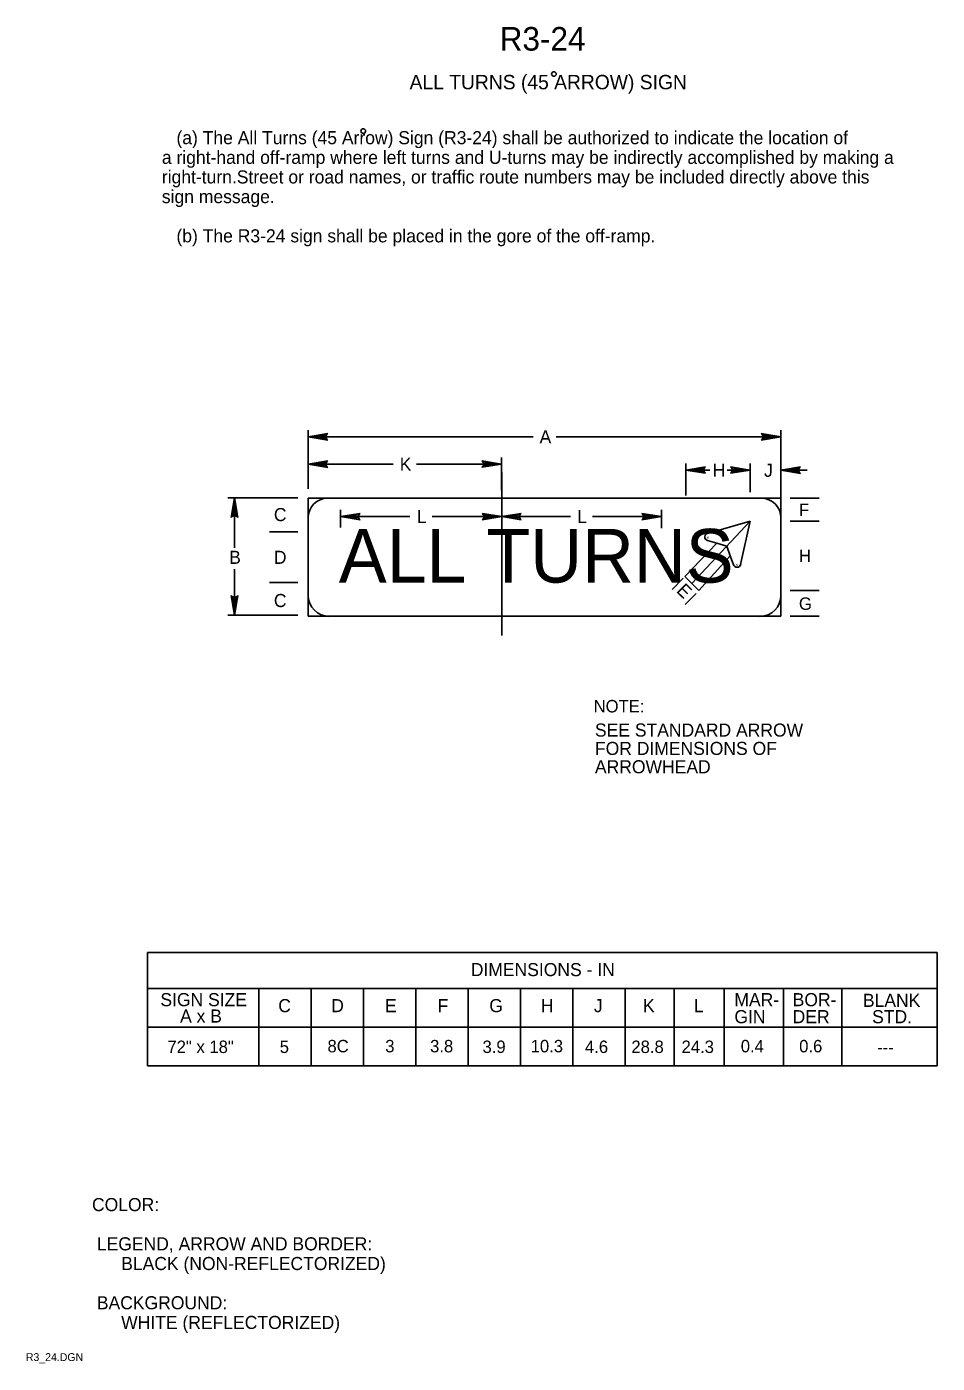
# Model space of a CAD drawing. Extents: x 0.5 to 7.3, y 0.2 to 10.2.
import ezdxf

# ---------------------------------------------------------------- set-up
doc = ezdxf.new("R2010")
doc.units = 0
for name, color, linetype in [('1', 7, 'Continuous'), ('11', 7, 'Continuous'), ('12', 7, 'Continuous'), ('2', 7, 'Continuous'), ('3', 7, 'Continuous')]:
    doc.layers.add(name, color=color, linetype=linetype)

# ---------------------------------------------------------------- blocks, each defined once
blk = doc.blocks.new('RARROW')
at = {"layer": '3'}
for p, q in [((-84.9, 11.2), (-89.2, 15.1)), ((-89.2, 15.1), (0, 0)), ((0, 0), (-89.2, -14.9)), ((-84.9, 11.2), (-81.7, 4.8)), ((0, 0), (-84.9, 11.2)), ((-84.6, -10.6), (0, 0)), ((-81.7, 4.8), (0, 0)), ((0, 0), (-81.7, -4.3)), ((-89.2, -14.9), (-84.6, -10.6)), ((-81.7, -4.3), (-84.6, -10.6))]:
    blk.add_line(p, q, dxfattribs=at)

msp = doc.modelspace()

# ---------------------------------------------------------------- linework, layer by layer
at = {"layer": '1'}
for centre in [(4.461, 9.849), (3.028, 9.42)]:
    msp.add_circle(centre, 0.0174, dxfattribs=at)
at = {"layer": '11'}
for p, q in [((2.614, 6.502), (2.614, 6.66)), ((2.614, 6.66), (2.772, 6.66)), ((6.009, 6.66), (6.167, 6.66)), ((6.167, 6.66), (6.167, 6.502)), ((2.614, 5.772), (2.614, 5.929)), ((6.167, 5.929), (6.167, 5.772)), ((2.772, 5.772), (2.614, 5.772)), ((6.167, 5.772), (6.009, 5.772))]:
    msp.add_line(p, q, dxfattribs=at)
at = {"layer": '12'}
for p, q in [((5.935, 6.487), (5.616, 6.395)), ((5.864, 6.161), (5.935, 6.487)), ((5.614, 6.341), (5.684, 6.321)), ((5.684, 6.321), (5.444, 6.07)), ((5.549, 5.966), (5.786, 6.225)), ((5.786, 6.225), (5.811, 6.159)), ((5.444, 6.07), (5.549, 5.966))]:
    msp.add_line(p, q, dxfattribs=at)
for centre, radius, start, end in [((5.623, 6.368), 0.0282, 104.7971, 250.7977), ((5.837, 6.168), 0.0281, 198.1274, 346.0897)]:
    msp.add_arc(centre, radius, start, end, dxfattribs=at)
at = {"layer": '3'}
for p, q in [((2.614, 6.88), (2.614, 7.17)), ((6.167, 6.722), (6.167, 7.17)), ((4.304, 7.121), (2.614, 7.121)), ((4.477, 7.121), (6.167, 7.121)), ((2.614, 6.729), (2.614, 6.965)), ((4.067, 6.719), (4.067, 6.965)), ((3.253, 6.916), (2.614, 6.916)), ((3.428, 6.916), (4.067, 6.916)), ((4.068, 6.853), (4.068, 5.626)), ((5.453, 6.847), (5.453, 6.921)), ((5.453, 6.679), (5.453, 6.921)), ((5.453, 6.871), (5.601, 6.896)), ((5.593, 6.889), (5.453, 6.871)), ((5.453, 6.871), (5.588, 6.878)), ((5.632, 6.871), (5.453, 6.871)), ((5.588, 6.864), (5.453, 6.871)), ((5.453, 6.871), (5.594, 6.853)), ((5.601, 6.847), (5.453, 6.871)), ((5.588, 6.878), (5.593, 6.889)), ((5.594, 6.853), (5.588, 6.864)), ((5.601, 6.896), (5.593, 6.889)), ((5.594, 6.853), (5.601, 6.847)), ((5.762, 6.871), (5.935, 6.871)), ((5.795, 6.89), (5.788, 6.896)), ((5.788, 6.896), (5.935, 6.871)), ((5.935, 6.871), (5.788, 6.847)), ((5.788, 6.847), (5.795, 6.854)), ((5.795, 6.89), (5.8, 6.879)), ((5.935, 6.871), (5.795, 6.89)), ((5.795, 6.854), (5.935, 6.871)), ((5.8, 6.864), (5.795, 6.854)), ((5.8, 6.879), (5.935, 6.871)), ((5.935, 6.871), (5.8, 6.864)), ((5.935, 6.706), (5.935, 6.921)), ((6.167, 6.66), (6.167, 6.921)), ((6.363, 6.871), (6.167, 6.871)), ((2.536, 6.662), (2.011, 6.662)), ((2.06, 6.286), (2.06, 6.662)), ((2.762, 6.66), (6.019, 6.66)), ((6.237, 6.66), (6.453, 6.66)), ((2.857, 6.438), (2.857, 6.571)), ((4.068, 6.452), (4.068, 6.571)), ((5.268, 6.433), (5.268, 6.571)), ((2.614, 6.512), (2.614, 5.929)), ((3.379, 6.521), (2.857, 6.521)), ((3.545, 6.521), (4.068, 6.521)), ((4.585, 6.521), (4.068, 6.521)), ((4.75, 6.521), (5.268, 6.521)), ((5.497, 6.018), (5.935, 6.487)), ((6.167, 5.929), (6.167, 6.512)), ((6.237, 6.487), (6.453, 6.487)), ((2.536, 6.407), (2.322, 6.407)), ((5.684, 6.321), (5.761, 6.3)), ((5.786, 6.225), (5.761, 6.3)), ((2.06, 6.127), (2.06, 5.781)), ((5.432, 6.058), (5.349, 5.974)), ((2.536, 6.025), (2.322, 6.025)), ((5.53, 5.944), (5.447, 5.86)), ((6.237, 5.966), (6.453, 5.966)), ((2.536, 5.781), (2.011, 5.781)), ((2.772, 5.772), (6.009, 5.772)), ((6.453, 5.772), (6.237, 5.772)), ((1.405, 3.243), (1.405, 2.392)), ((1.405, 3.243), (7.342, 3.243)), ((7.342, 3.243), (7.342, 2.392)), ((1.405, 2.972), (7.342, 2.972)), ((2.243, 2.972), (2.243, 2.392)), ((2.635, 2.972), (2.635, 2.392)), ((3.029, 2.972), (3.029, 2.392)), ((3.422, 2.972), (3.422, 2.392)), ((3.816, 2.972), (3.816, 2.392)), ((4.21, 2.972), (4.21, 2.392)), ((4.603, 2.972), (4.603, 2.392)), ((4.997, 2.972), (4.997, 2.392)), ((4.997, 2.972), (4.997, 2.392)), ((5.364, 2.972), (5.364, 2.392)), ((5.741, 2.972), (5.741, 2.392)), ((6.187, 2.972), (6.187, 2.392)), ((6.625, 2.972), (6.625, 2.392)), ((1.405, 2.682), (7.342, 2.682)), ((1.405, 2.392), (7.342, 2.392))]:
    msp.add_line(p, q, dxfattribs=at)
for centre, radius, start, end in [((2.762, 6.512), 0.148, 90, 180), ((6.019, 6.512), 0.148, 0, 90), ((2.772, 5.929), 0.158, 180, 270), ((6.009, 5.929), 0.158, 270, 0)]:
    msp.add_arc(centre, radius, start, end, dxfattribs=at)

# ---------------------------------------------------------------- block references
at = {"layer": '3', "xscale": 0.0016545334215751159, "yscale": 0.0016366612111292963}
for p, rotation in [((2.614, 7.121), 180), ((2.614, 6.916), 180), ((6.167, 6.871), 180), ((2.06, 6.662), 90), ((2.857, 6.521), 180), ((4.068, 6.521), 180), ((2.06, 5.781), -90)]:
    msp.add_blockref('RARROW', p, dxfattribs=dict(at, rotation=rotation))
for p in [(6.167, 7.121), (4.067, 6.916), (4.068, 6.521), (5.268, 6.521)]:
    msp.add_blockref('RARROW', p, dxfattribs=at)

# ---------------------------------------------------------------- texts
at = {"layer": '1'}
for s, height, p in [('R3-24', 0.1772, (4.053, 10.025)), ('ALL TURNS (45 ARROW) SIGN', 0.10828, (3.376, 9.734)), ('NOTE:', 0.0935, (4.759, 5.049)), ('SEE STANDARD ARROW', 0.09842, (4.769, 4.867)), ('FOR DIMENSIONS OF', 0.09842, (4.769, 4.729)), ('ARROWHEAD', 0.0984, (4.769, 4.591)), ('COLOR:', 0.0984, (0.989, 1.299)), (' LEGEND, ARROW AND BORDER:', 0.09842, (0.989, 1.004)), ('      BLACK (NON-REFLECTORIZED)', 0.09842, (0.989, 0.856)), (' BACKGROUND:', 0.09842, (0.989, 0.561)), ('      WHITE (REFLECTORIZED)', 0.09842, (0.989, 0.413)), ('R3_24.DGN', 0.0591, (0.492, 0.172))]:
    msp.add_text(s, height=height, dxfattribs=at).set_placement(p)
at = {"layer": '12'}
msp.add_text('ALL TURNS', height=0.4033, dxfattribs=at).set_placement((2.844, 6.025))
msp.add_text('+', height=0.031, rotation=46.8172, dxfattribs=at).set_placement((5.62, 6.344))
at = {"layer": '2'}
for s, p in [('   (a) The All Turns (45 Arrow) Sign (R3-24) shall be authorized to indicate the location of ', (1.514, 9.321)), ('a right-hand off-ramp where left turns and U-turns may be indirectly accomplished by making a ', (1.514, 9.173)), ('right-turn.Street or road names, or traffic route numbers may be included directly above this ', (1.514, 9.026)), ('sign message.', (1.514, 8.878)), ('   (b) The R3-24 sign shall be placed in the gore of the off-ramp.', (1.514, 8.583))]:
    msp.add_text(s, height=0.09842, dxfattribs=at).set_placement(p)
at = {"layer": '3'}
for s, height, p in [('A', 0.0984, (4.353, 7.072)), ('K', 0.0984, (3.302, 6.866)), ('H', 0.0984, (5.654, 6.822)), ('J', 0.0984, (6.04, 6.82)), ('C', 0.0984, (2.356, 6.487)), ('L', 0.0984, (3.43, 6.472)), ('L', 0.0984, (4.635, 6.472)), ('F', 0.0935, (6.302, 6.525)), ('B', 0.0984, (2.02, 6.166)), ('D', 0.0984, (2.356, 6.166)), ('H', 0.0935, (6.302, 6.18)), ('C', 0.0984, (2.356, 5.841)), ('G', 0.0935, (6.302, 5.82)), ('DIMENSIONS - IN', 0.09842, (3.836, 3.066)), ('SIGN SIZE', 0.0984, (1.503, 2.84)), ('MAR-', 0.0984, (5.817, 2.84)), ('BOR-', 0.0984, (6.255, 2.84)), ('BLANK', 0.0984, (6.783, 2.835)), ('A x B', 0.0984, (1.651, 2.717)), ('C', 0.0984, (2.389, 2.795)), ('D', 0.0984, (2.787, 2.795)), ('E', 0.0984, (3.191, 2.795)), ('F', 0.0984, (3.586, 2.795)), ('G', 0.0984, (3.975, 2.795)), ('H', 0.0984, (4.362, 2.795)), ('J', 0.0984, (4.761, 2.795)), ('K', 0.0984, (5.13, 2.795)), ('L', 0.0984, (5.512, 2.795)), ('GIN', 0.0984, (5.817, 2.712)), ('DER', 0.0984, (6.255, 2.712)), ('STD.', 0.0984, (6.852, 2.712)), ('72" x 18"', 0.0935, (1.556, 2.488)), ('5', 0.0935, (2.4, 2.488)), ('8C', 0.0935, (2.759, 2.493)), ('3', 0.0935, (3.193, 2.493)), ('3.8', 0.0935, (3.53, 2.493)), ('3.9', 0.0935, (3.924, 2.488)), ('10.3', 0.0935, (4.286, 2.493)), ('4.6', 0.0935, (4.694, 2.488)), ('28.8', 0.0935, (5.043, 2.488)), ('24.3', 0.0935, (5.42, 2.488)), ('0.4', 0.0935, (5.865, 2.493)), ('0.6', 0.0935, (6.304, 2.493)), ('---', 0.0935, (6.89, 2.485))]:
    msp.add_text(s, height=height, dxfattribs=at).set_placement(p)
for s, height, rotation, p in [('+', 0.031, 46.9263, (5.837, 6.14)), ('E', 0.0984, 315.5673, (5.376, 5.958))]:
    msp.add_text(s, height=height, rotation=rotation, dxfattribs=at).set_placement(p)

doc.saveas('drawing.dxf')
